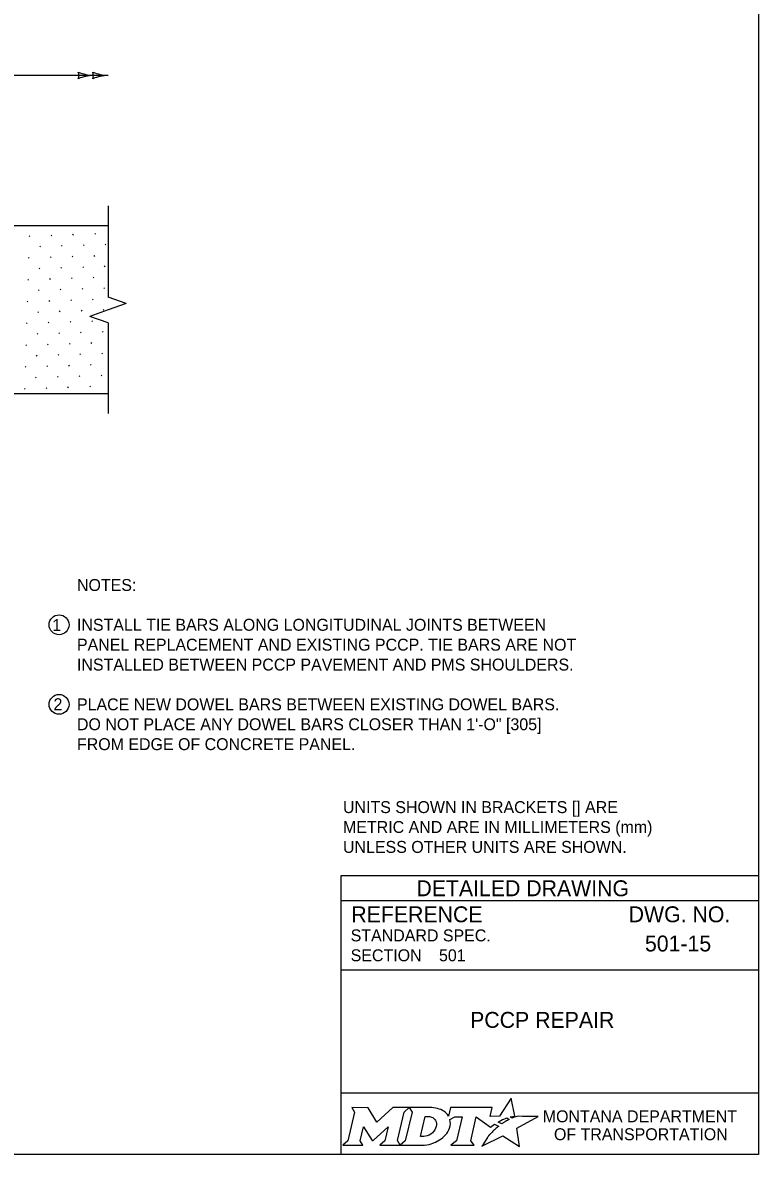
# Model space of a CAD drawing. Extents: x 49991.4 to 50021, y 49987.6 to 50011.4.
# Drawn here: x 50013.05 to 50016.75, y 49987.8 to 49993.49 of the extents above; entities that cross this region are included whole.
import ezdxf

# ---------------------------------------------------------------- set-up
doc = ezdxf.new("R2010")
doc.units = 0
for name, color, linetype in [('Default', 7, 'Continuous'), ('Level 1', 7, 'Continuous'), ('Level 17', 7, 'Continuous'), ('Level 2', 7, 'Continuous'), ('Level 3', 7, 'Continuous'), ('Level 5', 7, 'Continuous'), ('Level 6', 7, 'Continuous')]:
    doc.layers.add(name, color=color, linetype=linetype)

msp = doc.modelspace()

# ---------------------------------------------------------------- linework, layer by layer
at = {"layer": 'Default'}
for points in [[(50015.5126, 49987.9811), (50015.5023, 49987.9867), (50015.5139, 49987.9895), (50015.5255, 49987.9915), (50015.5081, 49988.0816), (50015.4486, 49987.9903), (50015.4013, 49987.9896), (50015.4116, 49988.0337), (50015.2024, 49988.0338), (50015.1923, 49987.9913), (50015.1865, 49987.9996)], [(50014.7056, 49988.0338), (50014.7197, 49988.0104), (50014.6862, 49987.8671), (50014.6605, 49987.8446), (50014.7621, 49987.8446), (50014.7486, 49987.8674), (50014.7648, 49987.9375), (50014.8085, 49987.8685), (50014.8138, 49987.8685), (50014.8889, 49987.938), (50014.8725, 49987.8669), (50014.8478, 49987.8449), (50014.9494, 49987.8449), (50014.9356, 49987.8682), (50014.9688, 49988.0106)], [(50014.9688, 49988.0106), (50014.9941, 49988.0338), (50014.9117, 49988.0338), (50014.8321, 49987.9608), (50014.7876, 49988.0335), (50014.7056, 49988.0338)], [(50015.1077, 49988.0338), (50014.9941, 49988.0338), (50015.0088, 49988.0109), (50014.9749, 49987.8671), (50014.9494, 49987.8449), (50015.06, 49987.8449)], [(50015.1317, 49987.9471), (50015.1305, 49987.939), (50015.1273, 49987.9297), (50015.1231, 49987.9215), (50015.1175, 49987.914), (50015.111, 49987.9071), (50015.1031, 49987.9008), (50015.0948, 49987.8961), (50015.0857, 49987.8922), (50015.0766, 49987.8899), (50015.0674, 49987.889), (50015.0515, 49987.889), (50015.0751, 49987.989), (50015.0911, 49987.989), (50015.0987, 49987.9884), (50015.1063, 49987.9865), (50015.1129, 49987.9835), (50015.119, 49987.9793), (50015.1238, 49987.9743), (50015.1275, 49987.9683), (50015.1302, 49987.9621), (50015.1318, 49987.9547), (50015.1318, 49987.9517), (50015.1317, 49987.9471)], [(50015.1991, 49987.9747), (50015.2237, 49987.9878), (50015.2606, 49987.9878), (50015.232, 49987.8673), (50015.2045, 49987.8446), (50015.3207, 49987.8446), (50015.3037, 49987.8675), (50015.3319, 49987.9877), (50015.4032, 49987.936), (50015.4243, 49987.9511), (50015.444, 49987.9402)], [(50015.3882, 49987.8843), (50015.3729, 49987.8599), (50015.3682, 49987.8524), (50015.3624, 49987.8438), (50015.3601, 49987.8395), (50015.4654, 49987.8926), (50015.5493, 49987.8375), (50015.5362, 49987.9302), (50015.6431, 49987.9886), (50015.5938, 49987.9894), (50015.5637, 49987.9898), (50015.5429, 49987.9901), (50015.5361, 49987.9886), (50015.5312, 49987.9874), (50015.5228, 49987.9851), (50015.5126, 49987.9811)], [(50015.4622, 49987.9535), (50015.4598, 49987.9518), (50015.4415, 49987.9614), (50015.4518, 49987.9671), (50015.4559, 49987.9693), (50015.4645, 49987.9733), (50015.4702, 49987.9759), (50015.4781, 49987.9789), (50015.4854, 49987.9816), (50015.4972, 49987.9742), (50015.4932, 49987.9721), (50015.4886, 49987.9696), (50015.4844, 49987.9674), (50015.4794, 49987.9645), (50015.4775, 49987.9634), (50015.4748, 49987.9618), (50015.4723, 49987.9604), (50015.47, 49987.9588), (50015.4674, 49987.957), (50015.4647, 49987.9552), (50015.4622, 49987.9535)], [(50015.1057, 49987.8522), (50015.1141, 49987.8548), (50015.1271, 49987.8602), (50015.1475, 49987.8712)], [(50015.4021, 49987.9004), (50015.4021, 49987.9004)]]:
    msp.add_lwpolyline(points, dxfattribs=at)
for centre, radius, start, end in [((50015.0868, 49987.9727), 0.1183, 300.9103, 339.1383), ((50015.1308, 49987.9554), 0.0709, 339.5329, 15.8582)]:
    msp.add_arc(centre, radius, start, end, dxfattribs=at)
for centre, major_axis, ratio, start_param, end_param in [((50015.1056, 49987.9864), (0.0834, -0.0037), 0.568097, 0.61298, 1.570796), ((50015.1612, 49987.9937), (0.0361, -0.0295), 0.469099, 1.225588, 1.570796), ((50015.4329, 49987.9305), (-0.0112, -0.0097), 0.021651, 3.157348, 6.283185), ((50015.3952, 49987.8923), (-0.00694, -0.00806), 0.008222, 0, 3.137361), ((50015.4119, 49987.9106), (-0.0098, -0.0102), 0.016458, 3.141593, 6.279097), ((50015.0603, 49987.9932), (0, 0.1484), 0.987302, 3.139398, 3.456847)]:
    msp.add_ellipse(centre, major_axis=major_axis, ratio=ratio, start_param=start_param, end_param=end_param, dxfattribs=at)
at = {"layer": 'Level 1'}
for p, q in [((50010.6596, 49992.4669), (50013.4804, 49992.4669)), ((50010.6456, 49991.6226), (50013.4804, 49991.6226))]:
    msp.add_line(p, q, dxfattribs=at)
msp.add_lwpolyline([(49999.3835, 49998.9992), (50016.7501, 49998.9992), (50016.7501, 49987.7988), (49999.3835, 49987.7988)], close=True, dxfattribs=at)
at = {"layer": 'Level 17'}
for p, q in [((50013.1942, 49992.4161), (50013.1977, 49992.4197)), ((50013.3038, 49992.4197), (50013.3073, 49992.4232)), ((50013.4134, 49992.4232), (50013.4169, 49992.4268)), ((50013.0846, 49992.4126), (50013.0881, 49992.4161)), ((50013.1376, 49992.3596), (50013.1411, 49992.3631)), ((50013.2472, 49992.3631), (50013.2507, 49992.3666)), ((50013.3568, 49992.3667), (50013.3604, 49992.3702)), ((50013.4664, 49992.3702), (50013.47, 49992.3737)), ((50013.081, 49992.303), (50013.0846, 49992.3065)), ((50013.1906, 49992.3065), (50013.1942, 49992.3101)), ((50013.3002, 49992.3101), (50013.3038, 49992.3136)), ((50013.4098, 49992.3136), (50013.4134, 49992.3172)), ((50013.1341, 49992.25), (50013.1376, 49992.2535)), ((50013.2437, 49992.2535), (50013.2472, 49992.257)), ((50013.3533, 49992.257), (50013.3568, 49992.2606)), ((50013.4629, 49992.2606), (50013.4664, 49992.2641)), ((50013.0775, 49992.1934), (50013.081, 49992.1969)), ((50013.1871, 49992.1969), (50013.1906, 49992.2005)), ((50013.2967, 49992.2005), (50013.3002, 49992.204)), ((50013.4063, 49992.204), (50013.4098, 49992.2075)), ((50013.1305, 49992.1404), (50013.134, 49992.1439)), ((50013.2401, 49992.1439), (50013.2437, 49992.1474)), ((50013.3497, 49992.1474), (50013.3533, 49992.151)), ((50013.4593, 49992.151), (50013.4629, 49992.1545)), ((50013.0739, 49992.0838), (50013.0775, 49992.0873)), ((50013.1835, 49992.0873), (50013.1871, 49992.0909)), ((50013.2932, 49992.0909), (50013.2967, 49992.0944)), ((50013.4028, 49992.0944), (50013.4063, 49992.0979)), ((50013.127, 49992.0307), (50013.1305, 49992.0343)), ((50013.2366, 49992.0343), (50013.2401, 49992.0378)), ((50013.3462, 49992.0378), (50013.3497, 49992.0414)), ((50013.4558, 49992.0414), (50013.4593, 49992.0449)), ((50013.0704, 49991.9742), (50013.0739, 49991.9777)), ((50013.18, 49991.9777), (50013.1835, 49991.9812)), ((50013.2896, 49991.9813), (50013.2931, 49991.9848)), ((50013.3992, 49991.9848), (50013.4028, 49991.9883)), ((50013.1234, 49991.9211), (50013.127, 49991.9247)), ((50013.233, 49991.9247), (50013.2366, 49991.9282)), ((50013.3426, 49991.9282), (50013.3462, 49991.9318)), ((50013.4523, 49991.9318), (50013.4558, 49991.9353)), ((50013.0669, 49991.8646), (50013.0704, 49991.8681)), ((50013.1765, 49991.8681), (50013.18, 49991.8716)), ((50013.2861, 49991.8716), (50013.2896, 49991.8752)), ((50013.3957, 49991.8752), (50013.3992, 49991.8787)), ((50013.1199, 49991.8115), (50013.1234, 49991.8151)), ((50013.2295, 49991.8151), (50013.233, 49991.8186)), ((50013.3391, 49991.8186), (50013.3426, 49991.8221)), ((50013.4487, 49991.8222), (50013.4522, 49991.8257)), ((50013.0633, 49991.755), (50013.0668, 49991.7585)), ((50013.1729, 49991.7585), (50013.1765, 49991.762)), ((50013.2825, 49991.762), (50013.2861, 49991.7656)), ((50013.3921, 49991.7656), (50013.3957, 49991.7691)), ((50013.1163, 49991.7019), (50013.1199, 49991.7055)), ((50013.226, 49991.7055), (50013.2295, 49991.709)), ((50013.3356, 49991.709), (50013.3391, 49991.7125)), ((50013.4452, 49991.7125), (50013.4487, 49991.7161)), ((50013.0598, 49991.6453), (50013.0633, 49991.6489)), ((50013.1694, 49991.6489), (50013.1729, 49991.6524)), ((50013.279, 49991.6524), (50013.2825, 49991.656)), ((50013.3886, 49991.656), (50013.3921, 49991.6595))]:
    msp.add_line(p, q, dxfattribs=at)
at = {"layer": 'Level 2'}
for centre in [(50013.2343, 49990.4606), (50013.2343, 49990.0606)]:
    msp.add_circle(centre, 0.05, dxfattribs=at)
at = {"layer": 'Level 3'}
msp.add_lwpolyline([(50013.4804, 49993.2222), (50010.6458, 49993.2222)], dxfattribs=at)
for centre, radius, start, end in [((50013.4162, 49993.4443), 0.2223, 247.456, 267.6395), ((50013.2788, 49993.2222), 0.0548, 342.1388, 17.8612), ((50013.4185, 49992.9895), 0.233, 92.8273, 112.0772), ((50013.4896, 49993.4443), 0.2223, 247.456, 267.6395), ((50013.3522, 49993.2222), 0.0548, 342.1388, 17.8612), ((50013.4919, 49992.9895), 0.233, 92.8273, 112.0772)]:
    msp.add_arc(centre, radius, start, end, dxfattribs=at)
at = {"layer": 'Level 5'}
for p, q in [((50016.7501, 49989.1988), (50014.6501, 49989.1988)), ((50014.6501, 49989.1988), (50014.6501, 49987.7988)), ((50016.7501, 49989.0738), (50014.6501, 49989.0738)), ((50016.3862, 49988.8587), (50016.3862, 49988.8587)), ((50015.1444, 49988.7993), (50015.1444, 49988.7993)), ((50016.7501, 49988.7238), (50014.6501, 49988.7238)), ((50015.7001, 49988.4747), (50015.7001, 49988.4747)), ((50016.7501, 49988.1057), (50014.6501, 49988.1057))]:
    msp.add_line(p, q, dxfattribs=at)
at = {"layer": 'Level 6'}
for p, q in [((50013.4804, 49992.5669), (50013.4804, 49992.1077)), ((50013.5718, 49992.0753), (50013.4804, 49992.1077)), ((50013.4804, 49992.0429), (50013.389, 49992.0105)), ((50013.5718, 49992.0753), (50013.4804, 49992.0429)), ((50013.4804, 49991.9781), (50013.389, 49992.0105)), ((50013.4804, 49991.9781), (50013.4804, 49991.5226))]:
    msp.add_line(p, q, dxfattribs=at)

# ---------------------------------------------------------------- texts
at = {"layer": 'Default'}
for s, p in [('MONTANA DEPARTMENT', (50015.6663, 49987.96)), ('OF TRANSPORTATION', (50015.7225, 49987.87))]:
    msp.add_text(s, height=0.06, dxfattribs=at).set_placement(p)
at = {"layer": 'Level 2'}
for s, height, p in [('NOTES:', 0.06, (50013.3243, 49990.6306)), ('1', 0.06, (50013.2003, 49990.4293)), ('INSTALL TIE BARS ALONG LONGITUDINAL JOINTS BETWEEN ', 0.06, (50013.3243, 49990.4306)), ('PANEL REPLACEMENT AND EXISTING PCCP. TIE BARS ARE NOT ', 0.06, (50013.3243, 49990.3306)), ('INSTALLED BETWEEN PCCP PAVEMENT AND PMS SHOULDERS.', 0.06, (50013.3243, 49990.2306)), ('2', 0.06, (50013.2065, 49990.0313)), ('PLACE NEW DOWEL BARS BETWEEN EXISTING DOWEL BARS.', 0.06, (50013.3243, 49990.0306)), ('DO NOT PLACE ANY DOWEL BARS CLOSER THAN 1\'-O" [305]', 0.06, (50013.3243, 49989.9306)), ('FROM EDGE OF CONCRETE PANEL.', 0.06, (50013.3243, 49989.8306)), ('UNITS SHOWN IN BRACKETS [] ARE ', 0.06, (50014.6618, 49989.5142)), ('METRIC AND ARE IN MILLIMETERS (mm) ', 0.06, (50014.6618, 49989.4142)), ('UNLESS OTHER UNITS ARE SHOWN.', 0.06, (50014.6618, 49989.3142)), ('501-15', 0.08, (50016.1798, 49988.8187)), ('501', 0.06, (50015.1444, 49988.7693)), ('PCCP REPAIR', 0.08, (50015.3009, 49988.4347))]:
    msp.add_text(s, height=height, dxfattribs=at).set_placement(p)
at = {"layer": 'Level 5'}
for s, height, p in [('DETAILED DRAWING', 0.0799, (50015.0311, 49989.0963)), ('REFERENCE', 0.08, (50014.7037, 49988.9654)), ('DWG. NO.', 0.08, (50016.0979, 49988.9654)), ('STANDARD SPEC.', 0.06, (50014.7004, 49988.8694)), ('SECTION', 0.06, (50014.7004, 49988.7694))]:
    msp.add_text(s, height=height, dxfattribs=at).set_placement(p)

doc.saveas('drawing.dxf')
